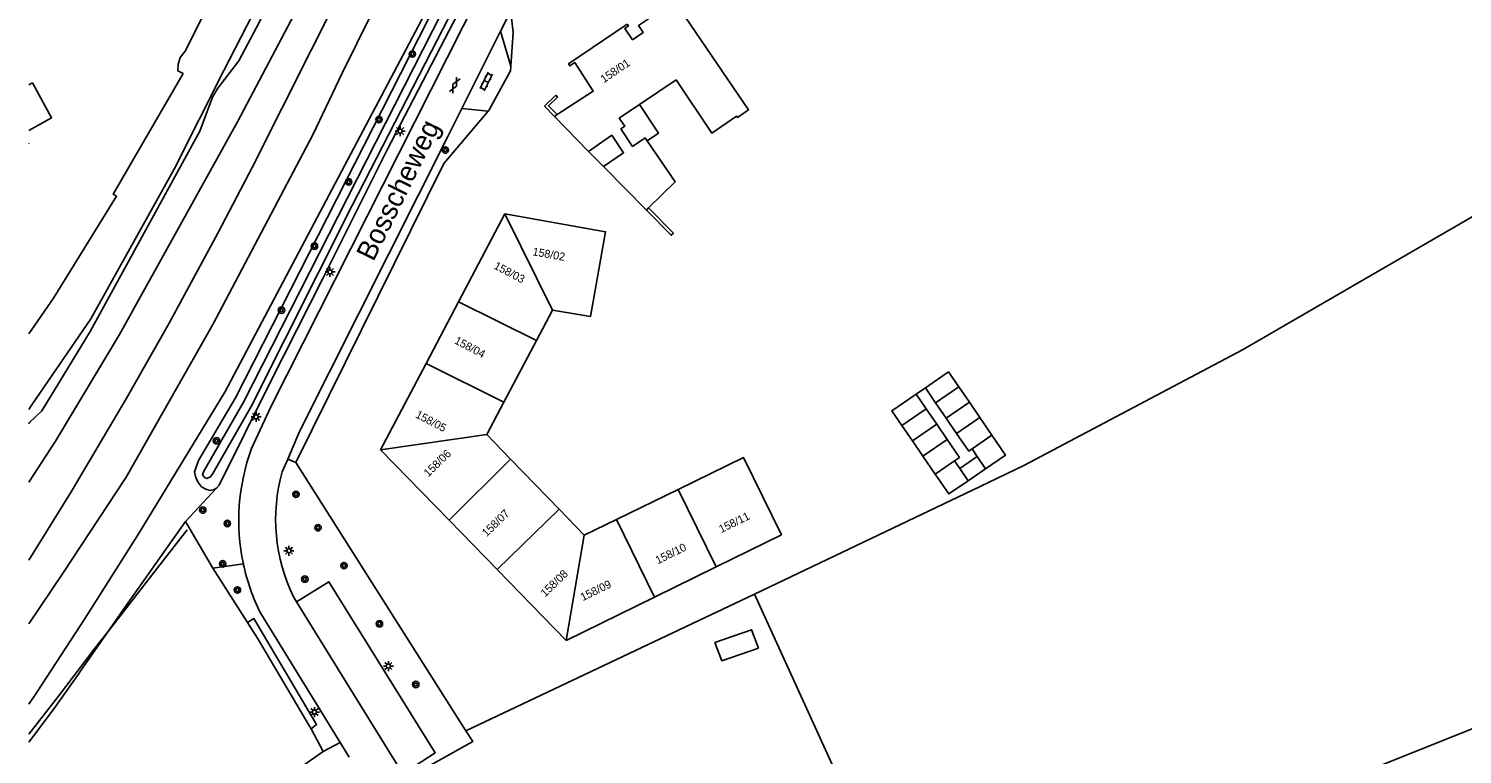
# Model space of a CAD drawing. Extents: x 135999 to 138000, y 396000 to 398501.
# Drawn here: x 136000 to 136179.2, y 397263.7 to 397354.4 of the extents above; entities that cross this region are included whole.
import ezdxf

# ---------------------------------------------------------------- set-up
doc = ezdxf.new("R2010")
doc.units = 0
for name, color, linetype in [('gg-afsc-erfafscheiding', 7, 'Continuous'), ('gg-afsc-hekwerk', 7, 'Continuous'), ('gg-afsc-muur', 7, 'Continuous'), ('gg-anno-huisnummerreeks BGT', 7, 'Continuous'), ('gg-anno-openbare ruimte label', 7, 'Continuous'), ('gg-aspt-spoorlijn', 7, 'Continuous'), ('gg-bbg-bijgebouw', 7, 'Continuous'), ('gg-bbg-gedigitaliseerde bebouwing', 7, 'Continuous'), ('gg-bbg-gedigitaliseerde bijgebouw', 7, 'Continuous'), ('gg-bbg-hoofdgebouw', 7, 'Continuous'), ('gg-bbg-luifel en loopbrug', 7, 'Continuous'), ('gg-bbg-overig bouwwerk', 7, 'Continuous'), ('gg-bbg-tussenscheiding', 7, 'Continuous'), ('gg-knt-bronhoudergrens', 7, 'Continuous'), ('gg-knt-verharding', 7, 'Continuous'), ('gg-kntw-beschoeiing', 7, 'Continuous'), ('gt-grn-groengrens', 7, 'Continuous'), ('gt-grn-weggrens', 7, 'Continuous'), ('gt-symb-boom', 7, 'Continuous'), ('gt-symb-gesloten verharding', 7, 'Continuous'), ('gt-symb-klinker verharding', 7, 'Continuous'), ('gt-symb-lichtmast', 7, 'Continuous'), ('gx-grn-maaiveld', 7, 'Continuous')]:
    doc.layers.add(name, color=color, linetype=linetype)

# ---------------------------------------------------------------- blocks, each defined once
blk = doc.blocks.new('gt0-KL1')
at = {"layer": 'gt-symb-klinker verharding'}
for p, q in [((-1.15, 0.3), (1.15, 0.3)), ((-1, -0.3), (-1, 0.3)), ((-0.5, 0.3), (-0.5, 0.45)), ((0, -0.3), (0, 0.3)), ((0.5, 0.3), (0.5, 0.45)), ((1, -0.3), (1, 0.3)), ((-1.15, -0.3), (1.15, -0.3)), ((-0.5, -0.45), (-0.5, -0.3)), ((0.5, -0.45), (0.5, -0.3))]:
    blk.add_line(p, q, dxfattribs=at)
blk = doc.blocks.new('gt0-LMAST')
at = {"layer": 'gt-symb-lichtmast'}
for p, q in [((-0.18, 0.17), (-0.45, 0.44)), ((-0.01, 0.25), (-0.01, 0.62)), ((0.17, 0.17), (0.44, 0.44)), ((-0.26, 0), (-0.63, 0)), ((-0.18, -0.18), (-0.45, -0.45)), ((-0.01, -0.25), (-0.01, -0.63)), ((0.44, -0.45), (0.17, -0.18)), ((0.24, 0), (0.62, 0))]:
    blk.add_line(p, q, dxfattribs=at)
blk.add_circle((-0.01, 0), 0.25, dxfattribs=at)
blk = doc.blocks.new('gt0-BOOM')
at = {"layer": 'gt-symb-boom'}
for radius in [0.4, 0.2]:
    blk.add_circle((0, 0), radius, dxfattribs=at)
blk = doc.blocks.new('gt0-GESVH1')
at = {"layer": 'gt-symb-gesloten verharding'}
for p, q in [((-0.99, -0.26), (0.01, 0.24)), ((0.01, -0.26), (-0.99, 0.24)), ((0.01, 0.24), (1.01, -0.26)), ((1.01, 0.24), (0.01, -0.26))]:
    blk.add_line(p, q, dxfattribs=at)

msp = doc.modelspace()

# ---------------------------------------------------------------- linework, layer by layer
at = {"layer": 'gg-afsc-erfafscheiding'}
msp.add_lwpolyline([(136034.92, 397383.12), (136027.16, 397366.74), (136019.54, 397351.6), (136018.95, 397350.8), (136018.68, 397349.98), (136018.65, 397349.14), (136019.3, 397348.8), (136010.56, 397333.74), (136010.98, 397333.47), (136003.1, 397320.72)], dxfattribs=at)
at = {"layer": 'gg-afsc-hekwerk'}
for p, q in [((136060.55, 397353.95), (136060.26, 397349.74)), ((136060.55, 397353.95), (136060.26, 397349.74)), ((136051.91, 397337.55), (136057.42, 397344.11)), ((136051.91, 397337.55), (136057.42, 397344.11)), ((136033.4, 397300.2), (136051.91, 397337.55)), ((136033.4, 397300.2), (136051.91, 397337.55)), ((136033.4, 397300.2), (136054.64, 397266.68)), ((136033.4, 397300.2), (136054.64, 397266.68)), ((136027.35, 397280.2), (136023.03, 397287.01)), ((136027.35, 397280.2), (136023.03, 397287.01)), ((136000, 397265.27), (136003.07, 397269.31)), ((136000, 397265.27), (136003.07, 397269.31)), ((136036.8, 397264.08), (136035.29, 397266.91)), ((136036.8, 397264.08), (136035.29, 397266.91))]:
    msp.add_line(p, q, dxfattribs=at)
for points in [[(136057.42, 397344.11), (136057.54, 397344.26), (136060.22, 397349.15), (136060.26, 397349.74)], [(136057.42, 397344.11), (136057.54, 397344.26), (136060.22, 397349.15), (136060.26, 397349.74)], [(136000, 397266.24), (136003.72, 397271.01), (136008.3, 397277.03), (136010.53, 397279.84), (136015.12, 397285.76), (136019.81, 397291.77)], [(136035.29, 397266.91), (136035.1, 397267.26), (136028.6, 397278.24), (136027.35, 397280.2)], [(136035.29, 397266.91), (136035.1, 397267.26), (136028.6, 397278.24), (136027.35, 397280.2)], [(136054.64, 397266.68), (136055.51, 397265.32), (136048.8, 397261.58), (136058.58, 397245.94)], [(136034.72, 397259.09), (136033.74, 397261.9), (136036.8, 397264.08)], [(136034.72, 397259.09), (136033.74, 397261.9), (136036.8, 397264.08)]]:
    msp.add_lwpolyline(points, dxfattribs=at)
at = {"layer": 'gg-afsc-muur'}
msp.add_line((136071.84, 397337.21), (136069.99, 397339.09), dxfattribs=at)
for points in [[(136065.71, 397343.46), (136064.48, 397344.72), (136065.88, 397346.1), (136066.09, 397345.88), (136064.96, 397344.78), (136066.05, 397343.68)], [(136077.49, 397332.02), (136080.58, 397328.87), (136080.3, 397328.6), (136077.21, 397331.74)]]:
    msp.add_lwpolyline(points, dxfattribs=at)
at = {"layer": 'gg-aspt-spoorlijn'}
for points in [[(136000, 397287.99), (136005.3, 397296.53), (136012.19, 397308.15), (136017.55, 397317.61), (136023.66, 397328.88), (136027.93, 397337.07), (136046.52, 397374.06), (136063.62, 397408.26)], [(136000, 397297.75), (136003.37, 397302.88), (136011.34, 397316.21), (136026.12, 397342.77), (136035.16, 397359.96), (136044.56, 397378.4), (136058.34, 397406.12)]]:
    msp.add_lwpolyline(points, dxfattribs=at)
at = {"layer": 'gg-bbg-bijgebouw'}
for p, q in [((136000, 397347.4), (136000.47, 397347.66)), ((136114.97, 397311.53), (136112.07, 397309.54)), ((136116.25, 397309.65), (136114.97, 397311.53)), ((136117.57, 397307.73), (136116.25, 397309.65)), ((136118.88, 397305.82), (136117.57, 397307.73)), ((136120.39, 397303.61), (136118.88, 397305.82)), ((136109.14, 397304.81), (136110.45, 397302.9)), ((136110.45, 397302.9), (136111.75, 397301)), ((136111.75, 397301), (136113.29, 397298.75)), ((136117.41, 397297.93), (136119.61, 397299.43))]:
    msp.add_line(p, q, dxfattribs=at)
for points in [[(136110.91, 397308.75), (136107.87, 397306.67), (136109.14, 397304.81)], [(136119.61, 397299.43), (136122.09, 397301.13), (136120.39, 397303.61)], [(136113.29, 397298.75), (136114.99, 397296.27), (136117.41, 397297.93)]]:
    msp.add_lwpolyline(points, dxfattribs=at)
at = {"layer": 'gg-bbg-gedigitaliseerde bebouwing'}
msp.add_lwpolyline([(136000, 397340.01), (136000.02, 397340.03), (136000, 397340.05)], dxfattribs=at)
at = {"layer": 'gg-bbg-gedigitaliseerde bijgebouw'}
for p, q in [((136110.91, 397308.75), (136112.18, 397306.89)), ((136112.07, 397309.54), (136113.35, 397307.66)), ((136112.18, 397306.89), (136113.49, 397304.99)), ((136114.67, 397305.74), (136113.35, 397307.66)), ((136113.49, 397304.99), (136114.79, 397303.08)), ((136115.98, 397303.83), (136114.67, 397305.74)), ((136117.91, 397301.91), (136118.56, 397300.95)), ((136116.37, 397299.45), (136115.71, 397300.41)), ((136116.37, 397299.45), (136118.56, 397300.95))]:
    msp.add_line(p, q, dxfattribs=at)
for points in [[(136000.47, 397347.66), (136002.86, 397343.27), (136000, 397341.71)], [(136114.79, 397303.08), (136116.33, 397300.83), (136115.71, 397300.41)], [(136115.98, 397303.83), (136117.49, 397301.62), (136117.91, 397301.91)]]:
    msp.add_lwpolyline(points, dxfattribs=at)
at = {"layer": 'gg-bbg-hoofdgebouw'}
for p, q in [((136066.05, 397343.68), (136065.71, 397343.46)), ((136065.71, 397343.46), (136069.99, 397339.09)), ((136077.21, 397331.74), (136071.84, 397337.21)), ((136077.49, 397332.02), (136077.21, 397331.74)), ((136059.53, 397331.29), (136053.73, 397320.29)), ((136053.73, 397320.29), (136049.68, 397312.59)), ((136063.47, 397315.44), (136065.47, 397319.22)), ((136059.4, 397307.75), (136063.47, 397315.44)), ((136049.68, 397312.59), (136043.99, 397301.8)), ((136057.26, 397303.7), (136059.4, 397307.75)), ((136060.23, 397300.64), (136057.26, 397303.7)), ((136043.99, 397301.8), (136052.55, 397293)), ((136066.29, 397294.38), (136060.23, 397300.64)), ((136081.18, 397296.84), (136073.46, 397293.1)), ((136069.42, 397291.14), (136066.29, 397294.38)), ((136052.55, 397293), (136058.55, 397286.83)), ((136073.46, 397293.1), (136069.42, 397291.14)), ((136078.24, 397283.38), (136085.94, 397287.16)), ((136058.55, 397286.83), (136067.19, 397277.95)), ((136067.19, 397277.95), (136078.24, 397283.38))]:
    msp.add_line(p, q, dxfattribs=at)
for points in [[(136074.79, 397355), (136074.96, 397354.76), (136074.52, 397354.45), (136075.48, 397353.04), (136076.8, 397353.94), (136076.23, 397354.82), (136079.24, 397356.83)], [(136076.34, 397344.94), (136080.91, 397348.01), (136085.37, 397341.37), (136088.47, 397343.47), (136088.58, 397343.32), (136089.98, 397344.29), (136080.74, 397357.84), (136079.24, 397356.83)], [(136066.05, 397343.68), (136070.57, 397346.59), (136068.26, 397350.18), (136067.62, 397349.76), (136067.46, 397350.01), (136074.79, 397355)], [(136076.34, 397344.94), (136073.82, 397343.25), (136074.51, 397342.22), (136074.02, 397341.89), (136075.49, 397339.7), (136077.05, 397340.76), (136077.29, 397340.4)], [(136071.84, 397337.21), (136074.36, 397338.92), (136072.87, 397341.12), (136069.99, 397339.09)], [(136077.29, 397340.4), (136080.8, 397335.26), (136077.49, 397332.02)], [(136065.47, 397319.22), (136070.24, 397318.46), (136072.11, 397329.04), (136059.53, 397331.29)], [(136085.94, 397287.16), (136094.09, 397291.17), (136089.35, 397300.81), (136081.18, 397296.84)]]:
    msp.add_lwpolyline(points, dxfattribs=at)
at = {"layer": 'gg-bbg-luifel en loopbrug'}
msp.add_line((136112.07, 397309.54), (136110.91, 397308.75), dxfattribs=at)
msp.add_lwpolyline([(136077.29, 397340.4), (136078.73, 397341.38), (136076.34, 397344.94)], dxfattribs=at)
at = {"layer": 'gg-bbg-overig bouwwerk'}
msp.add_lwpolyline([(136085.77, 397277.7), (136086.65, 397275.4), (136091.2, 397277.01), (136090.33, 397279.31), (136085.77, 397277.7)], dxfattribs=at)
at = {"layer": 'gg-bbg-tussenscheiding'}
for p, q in [((136065.47, 397319.22), (136059.53, 397331.29)), ((136063.47, 397315.44), (136053.73, 397320.29)), ((136059.4, 397307.75), (136049.68, 397312.59)), ((136113.35, 397307.66), (136116.25, 397309.65)), ((136112.18, 397306.89), (136109.14, 397304.81)), ((136117.57, 397307.73), (136114.67, 397305.74)), ((136113.49, 397304.99), (136110.45, 397302.9)), ((136118.88, 397305.82), (136115.98, 397303.83)), ((136057.26, 397303.7), (136043.99, 397301.8)), ((136114.79, 397303.08), (136111.75, 397301)), ((136120.39, 397303.61), (136117.91, 397301.91)), ((136060.23, 397300.64), (136052.55, 397293)), ((136115.71, 397300.41), (136113.29, 397298.75)), ((136118.56, 397300.95), (136119.61, 397299.43)), ((136117.41, 397297.93), (136116.37, 397299.45)), ((136081.18, 397296.84), (136085.94, 397287.16)), ((136058.55, 397286.83), (136066.29, 397294.38)), ((136073.46, 397293.1), (136078.24, 397283.38)), ((136069.42, 397291.14), (136067.19, 397277.95))]:
    msp.add_line(p, q, dxfattribs=at)
at = {"layer": 'gg-knt-bronhoudergrens'}
msp.add_line((136090.71, 397283.74), (136054.64, 397266.68), dxfattribs=at)
for points in [[(136124.38, 397299.84), (136151.7, 397314.28), (136182.19, 397331.94), (136212.18, 397355.58), (136245.51, 397385.61), (136260.68, 397399.7), (136271.32, 397407.73), (136274.95, 397410.47), (136279.27, 397412.69)], [(136090.71, 397283.74), (136100.89, 397261.46), (136058.62, 397245.86)]]:
    msp.add_lwpolyline(points, dxfattribs=at)
at = {"layer": 'gg-knt-verharding'}
for p, q in [((136058.98, 397354.09), (136060.26, 397356.63)), ((136054.14, 397344.44), (136058.98, 397354.09)), ((136060.26, 397349.74), (136058.98, 397354.09)), ((136052.39, 397340.96), (136054.14, 397344.44)), ((136054.14, 397344.44), (136057.42, 397344.11)), ((136031.7, 397299.04), (136032.38, 397300.64)), ((136033.49, 397282.79), (136033.1, 397283.42)), ((136046.77, 397261.3), (136033.49, 397282.79)), ((136038.95, 397265.21), (136029, 397281.33)), ((136040.07, 397263.39), (136038.95, 397265.21))]:
    msp.add_line(p, q, dxfattribs=at)
for points in [[(136027.86, 397301.95), (136030.25, 397307.15), (136070.29, 397386.42)], [(136032.38, 397300.64), (136033.86, 397304.09), (136052.39, 397340.96)], [(136046.77, 397261.3), (136050.81, 397263.93), (136037.53, 397285.29), (136033.49, 397282.79)]]:
    msp.add_lwpolyline(points, dxfattribs=at)
for centre, radius, start, end in [((136052.31, 397292.96), 26.05, 159.8207, 192.0177), ((136052.9, 397293.06), 22.03, 164.2618, 205.9783), ((136052.29, 397292.95), 26.03, 192.0064, 206.517)]:
    msp.add_arc(centre, radius, start, end, dxfattribs=at)
at = {"layer": 'gg-kntw-beschoeiing'}
msp.add_lwpolyline([(136077.48, 397219.15), (136077.1, 397220.07), (136076.13, 397222.44), (136075.17, 397224.82), (136098.82, 397234.31), (136122.35, 397243.71), (136134.07, 397248.39), (136145.9, 397253.1), (136157.68, 397257.84), (136174.15, 397264.42), (136188.22, 397270.04), (136204.63, 397276.61), (136235.19, 397288.8), (136251.57, 397295.36), (136286.82, 397309.44), (136298.53, 397314.14), (136317.37, 397321.48), (136331.55, 397326.93)], dxfattribs=at)
at = {"layer": 'gt-grn-groengrens'}
for p, q in [((136060.55, 397353.95), (136060.36, 397355.79)), ((136033.4, 397300.2), (136032.38, 397300.64)), ((136023.03, 397287.01), (136026.83, 397287.54))]:
    msp.add_line(p, q, dxfattribs=at)
msp.add_lwpolyline([(136027.35, 397280.2), (136028.16, 397280.7), (136035.99, 397267.44), (136035.29, 397266.91)], dxfattribs=at)
at = {"layer": 'gt-grn-weggrens'}
msp.add_line((136038.95, 397265.21), (136036.8, 397264.08), dxfattribs=at)
at = {"layer": 'gx-grn-maaiveld'}
for p, q in [((136000, 397316.29), (136003.1, 397320.72)), ((136019.61, 397292.81), (136023.47, 397297.01)), ((136023.47, 397297.01), (136023.79, 397297.36)), ((136019.61, 397292.81), (136023.03, 397287.01)), ((136003.07, 397269.31), (136006.32, 397273.86))]:
    msp.add_line(p, q, dxfattribs=at)
for points in [[(136000, 397280.02), (136004.31, 397286.4), (136012.18, 397298.36), (136023.01, 397317.44), (136035.53, 397341.17), (136039.17, 397348.87), (136046.54, 397363.8), (136052.08, 397374.2), (136057.88, 397386.51), (136065.43, 397400.65), (136065.92, 397402.13), (136065.85, 397403.17), (136067.45, 397406.27)], [(136051.35, 397401.88), (136051.67, 397401.69), (136036.55, 397371.16), (136028.86, 397355.28), (136026.27, 397350.39), (136023.63, 397346.99), (136022.98, 397345.86), (136021.4, 397341.6), (136007.69, 397316.58), (136001.64, 397306.65), (136000.1, 397305.21), (136000, 397305.03)], [(136000, 397306.82), (136000.38, 397307.4), (136007.78, 397318.16), (136018.21, 397336.95), (136024.4, 397349.21), (136040.22, 397379.99), (136051.35, 397401.88)], [(136000, 397269.99), (136001.06, 397271.53), (136007.08, 397280.74), (136013.83, 397291.41), (136024.51, 397309.01), (136055.25, 397367.17), (136066.48, 397388.62)], [(136023.47, 397297.01), (136023.08, 397296.77), (136022.68, 397296.72), (136022.16, 397296.86), (136021.61, 397297.18), (136021.21, 397297.65), (136020.9, 397298.28), (136020.72, 397299.03), (136021.23, 397300.47), (136025.86, 397308.28), (136063.7, 397382.62), (136064.65, 397384.26), (136065.37, 397385.07), (136065.82, 397385.26), (136066.42, 397385.16), (136066.92, 397384.8), (136067.41, 397384.16)], [(136026.83, 397307.74), (136064.69, 397382.11), (136065.43, 397383.51), (136065.67, 397383.74), (136065.92, 397383.8), (136066.25, 397383.42), (136066.1, 397382.99), (136054.08, 397358.96), (136040.43, 397332.31), (136027.79, 397307.22), (136023.02, 397298.82), (136022.71, 397298.41), (136022.25, 397298.19), (136021.99, 397298.33), (136021.74, 397298.66), (136021.9, 397299.11), (136026.83, 397307.74)], [(136067.41, 397384.16), (136067.41, 397383.87), (136067.14, 397383.23), (136054.82, 397358.58), (136044.78, 397339.21), (136036.78, 397323.19), (136030.26, 397310.38), (136023.79, 397297.36)], [(136370.38, 397341.94), (136362.16, 397338.77), (136331.55, 397326.93), (136317.37, 397321.48), (136298.53, 397314.14), (136286.82, 397309.44), (136251.57, 397295.36), (136235.19, 397288.8), (136204.63, 397276.61), (136188.22, 397270.04), (136174.15, 397264.42), (136157.68, 397257.84), (136145.9, 397253.1), (136134.07, 397248.39), (136122.35, 397243.71), (136098.82, 397234.31), (136075.17, 397224.82)], [(136090.71, 397283.74), (136118.93, 397297.2), (136124.38, 397299.84)], [(136019.61, 397292.81), (136012.67, 397283.04), (136006.45, 397274.07), (136006.32, 397273.86)]]:
    msp.add_lwpolyline(points, dxfattribs=at)

# ---------------------------------------------------------------- block references
at = {"layer": 'gt-symb-boom'}
for p in [(136047.95, 397351.25), (136043.78, 397343.06), (136039.99, 397335.27), (136035.72, 397327.23), (136031.6, 397319.24), (136023.47, 397302.91), (136033.41, 397296.23), (136021.76, 397294.26), (136024.83, 397292.58), (136036.17, 397292.05), (136024.25, 397287.54), (136039.41, 397287.31), (136034.52, 397285.63), (136026.09, 397284.27), (136043.84, 397280.05), (136048.38, 397272.46)]:
    msp.add_blockref('gt0-BOOM', p, dxfattribs=at)
at = {"layer": 'gt-symb-boom', "rotation": -25.53973281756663}
msp.add_blockref('gt0-BOOM', (136052.08, 397339.25), dxfattribs=at)
at = {"layer": 'gt-symb-gesloten verharding', "rotation": 63.33249782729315}
msp.add_blockref('gt0-GESVH1', (136053.24, 397347.36), dxfattribs=at)
at = {"layer": 'gt-symb-klinker verharding', "rotation": -116.36005820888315}
msp.add_blockref('gt0-KL1', (136057.19, 397347.82), dxfattribs=at)
at = {"layer": 'gt-symb-lichtmast'}
for p in [(136046.44, 397341.62), (136037.67, 397324.02), (136028.43, 397305.91), (136032.54, 397289.18), (136044.97, 397274.77), (136035.73, 397269.02)]:
    msp.add_blockref('gt0-LMAST', p, dxfattribs=at)

# ---------------------------------------------------------------- texts
at = {"layer": 'gg-anno-huisnummerreeks BGT'}
for s, rotation, p in [('158/01', 34.2, (136071.89, 397347.59)), ('158/02', 349.9, (136062.92, 397326.11)), ('158/03', 332.2, (136058.05, 397324.48)), ('158/04', 332.2, (136053.12, 397315.13)), ('158/05', 332.2, (136048.25, 397305.88)), ('158/06', 44.2, (136049.96, 397298.34)), ('158/07', 44.2, (136057.24, 397290.86)), ('158/11', 26.2, (136086.56, 397291.36)), ('158/10', 26.2, (136078.63, 397287.47)), ('158/08', 44.2, (136064.56, 397283.33)), ('158/09', 26.2, (136069.26, 397282.86))]:
    msp.add_text(s, height=1, rotation=rotation, dxfattribs=at).set_placement(p)
at = {"layer": 'gg-anno-openbare ruimte label'}
msp.add_text('Bosscheweg', height=2.5, rotation=63.8, dxfattribs=at).set_placement((136043.09, 397325.22))

doc.saveas('drawing.dxf')
